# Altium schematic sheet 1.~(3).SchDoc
size 420 x 297 mm
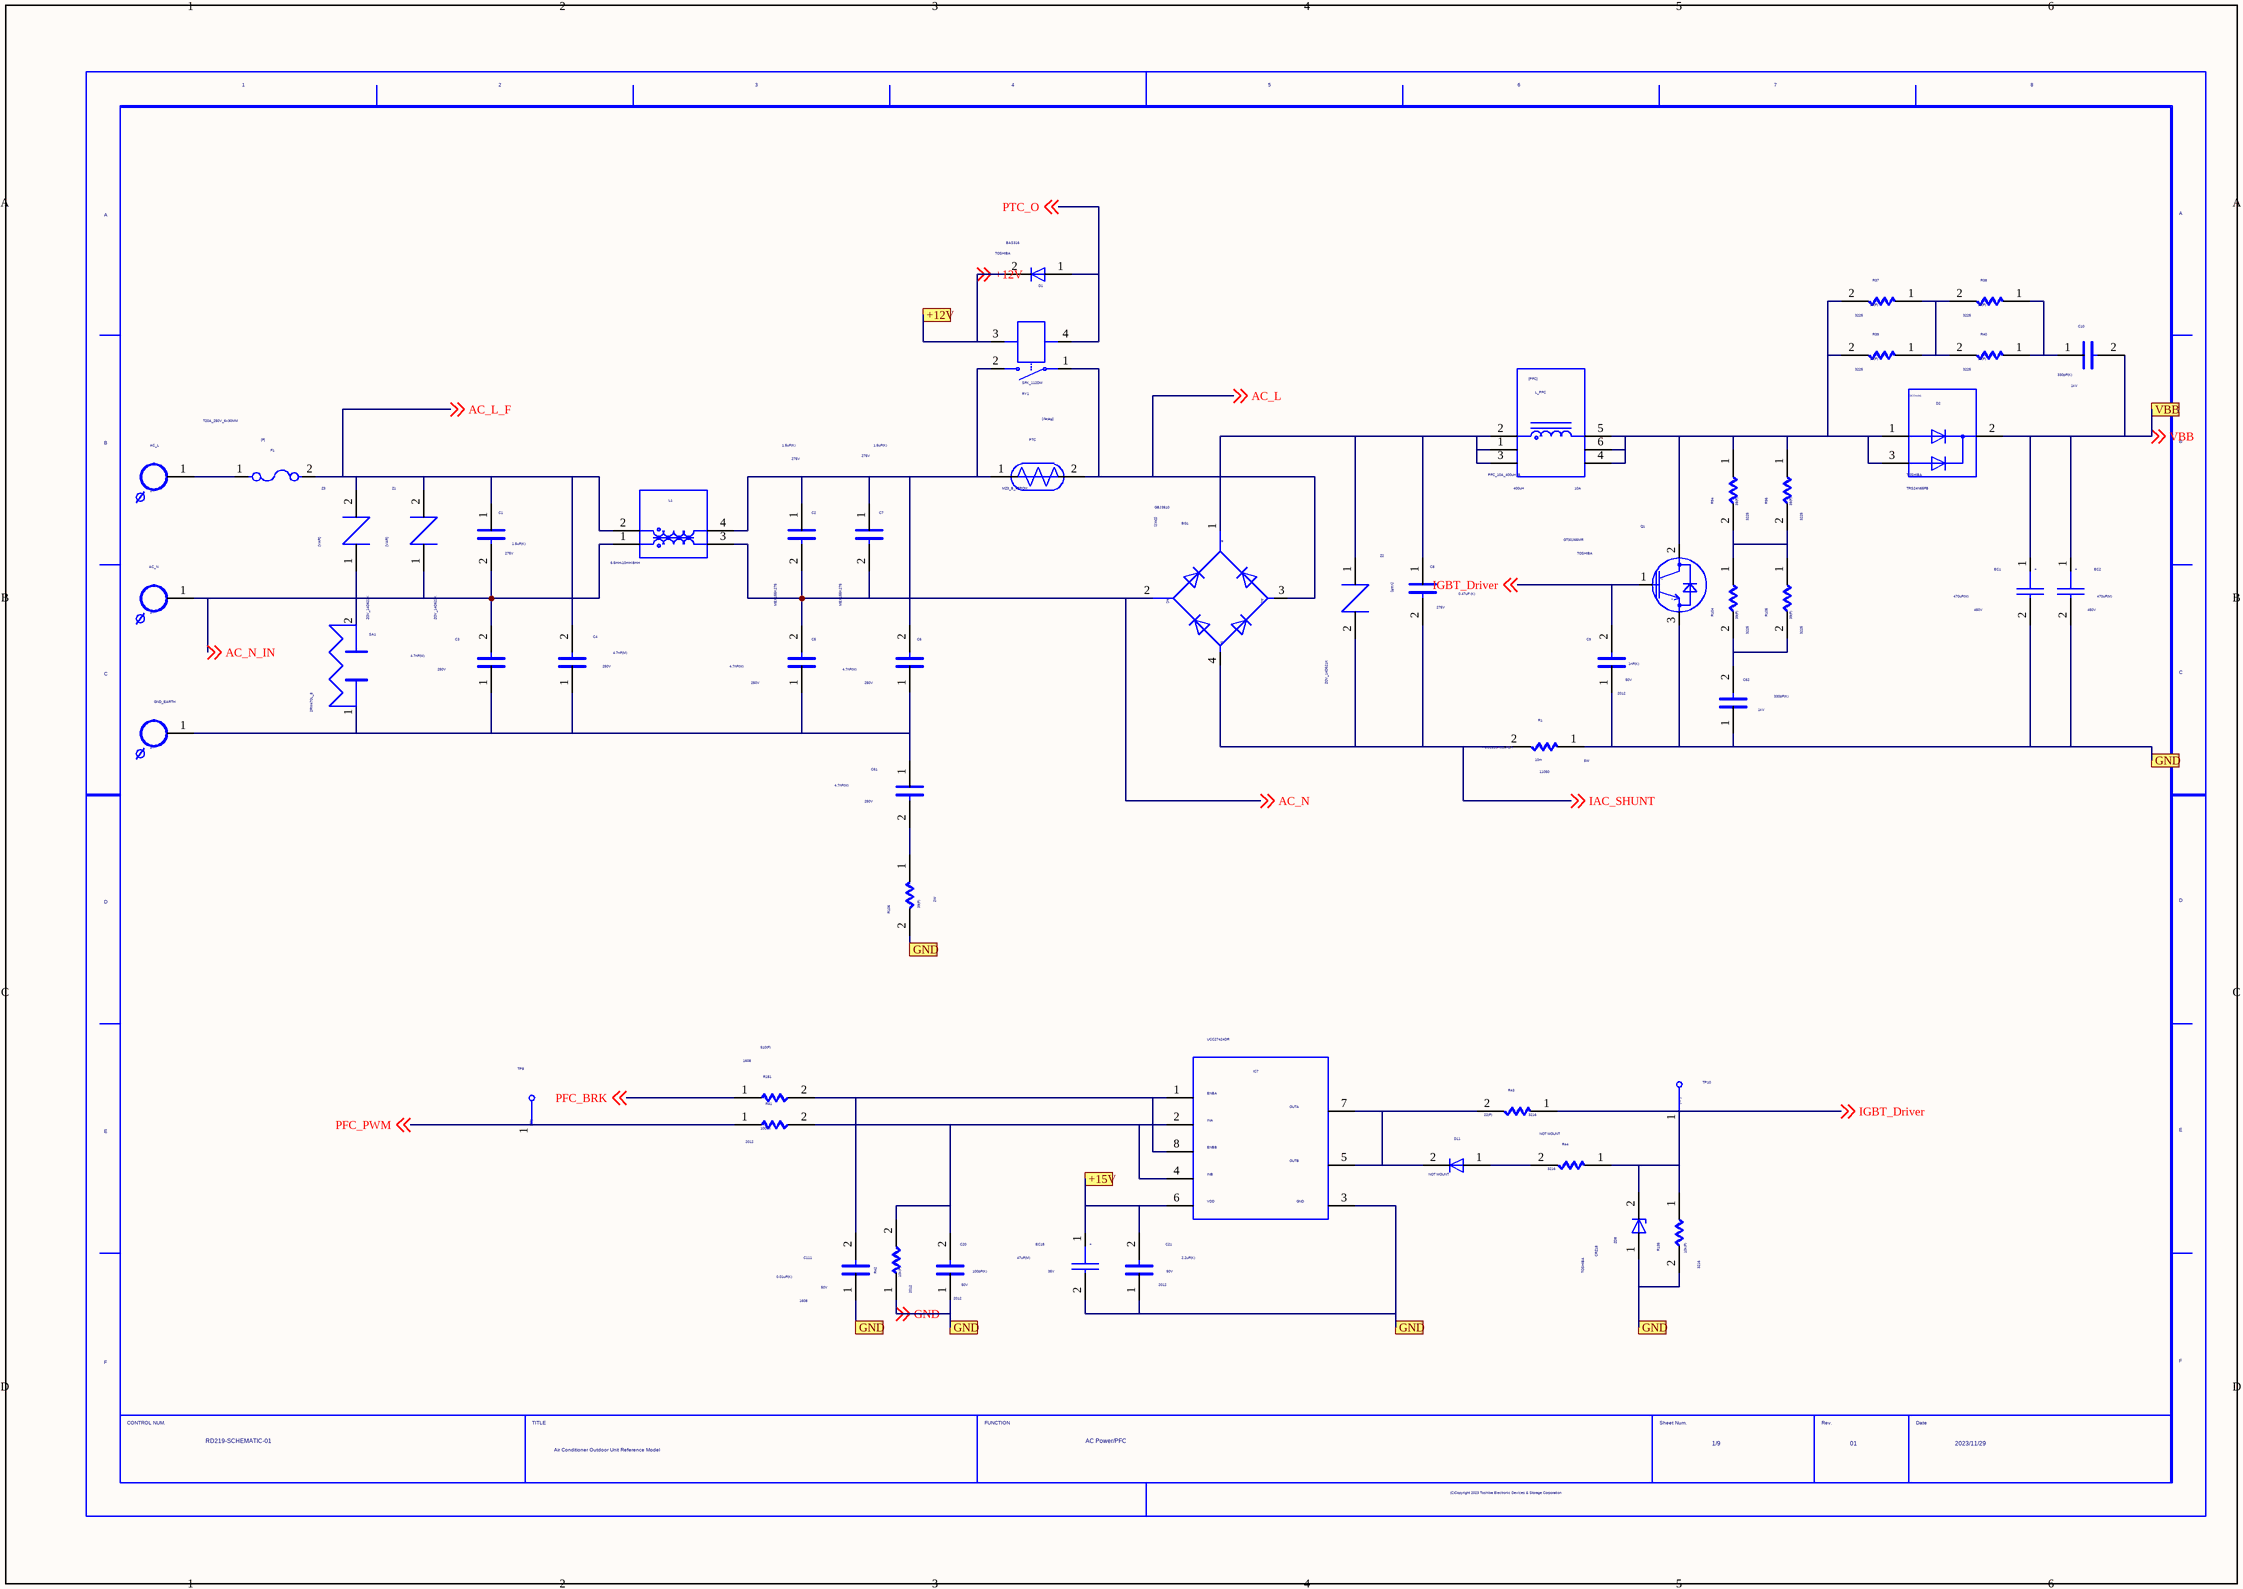
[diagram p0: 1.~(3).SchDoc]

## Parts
AC_L  TB1Y  (value not drawn)
AC_N  TB1Y  (value not drawn)
BG1  VAL1: GBJ3510  (hidden comment: DMJ)
C1  VAL2: 275V  VAL1: 1.5uF(K)  (hidden comment: C)
C2  VAL2: 275V  VAL1: 1.5uF(K)  VAL3: MEX155K275  (hidden comment: C)
C3  VAL2: 250V  VAL1: 4.7nF(M)  (hidden comment: C)
C4  VAL2: 250V  VAL1: 4.7nF(M)  (hidden comment: C)
C5  VAL2: 250V  VAL1: 4.7nF(M)  (hidden comment: C)
C6  VAL2: 250V  VAL1: 4.7nF(M)  (hidden comment: C)
C7  VAL2: 275V  VAL1: 1.5uF(K)  VAL3: MEX155K275  (hidden comment: C)
C8  VAL2: 275V  VAL1: 0.47uF (K)  (hidden comment: C)
C9  SIZECODESMD: 2012  VAL2: 50V  VAL1: 1nF(K)  (hidden comment: C)
C10  VAL2: 1kV  VAL1: 330pF(K)  (hidden comment: C)
C20  SIZECODESMD: 2012  VAL2: 50V  VAL1: 100pF(K)  (hidden comment: C)
C21  SIZECODESMD: 2012  VAL2: 50V  VAL1: 2.2uF(K)  (hidden comment: C)
C61  VAL2: 250V  VAL1: 4.7nF(M)  (hidden comment: C)
C62  VAL2: 1kV  VAL1: 330pF(K)  (hidden comment: C)
C111  SIZECODESMD: 1608  VAL2: 50V  VAL1: 0.01uF(K)  (hidden comment: C)
D1  USERCOMPTEXT3: TOSHIBA  VAL3: BAS316  (hidden comment: D_CUSTOM)
D2  USERCOMPTEXT3: TOSHIBA  VAL3: TRS24N65FB  (hidden comment: TRS24N)
D11  NOTMOUNT: NOT MOUNT  (hidden comment: D_CUSTOM)
EC1  VAL2: 450V  VAL1: 470uF(M)  (hidden comment: EC)
EC2  VAL2: 450V  VAL1: 470uF(M)  (hidden comment: EC)
EC15  VAL2: 35V  VAL1: 47uF(M)  (hidden comment: EC)
F1  COMP: T20A_250V_6x30MM  (hidden comment: F)
GND_EARTH  TB1Y  (value not drawn)
IC7  VAL1: UCC27424DR  (hidden comment: UCC27424)
L1  COMPCOMMENT: 6.5mH-10mH:8mH  (hidden comment: L2Y)
L_PFC  VAL3: PFC_10A_400uH_B  VAL2: 10A  VAL1: 400uH  (hidden comment: PFC)
PTC  VAL1: MZ3_B_47ROM  (hidden comment: PTC)
Q1  USERCOMPTEXT3: TOSHIBA  VAL3: GT30J65MR  (hidden comment: IGBT)
R1  SIZECODESMD: 11050  VAL3: FCSL110R010FER  VAL2: 5W  VAL1: 10m  (hidden comment: R)
R37  SIZECODESMD: 3225  VAL1: 39(F)  (hidden comment: R)
R38  SIZECODESMD: 3225  VAL1: 39(F)  (hidden comment: R)
R39  SIZECODESMD: 3225  VAL1: 39(F)  (hidden comment: R)
R40  SIZECODESMD: 3225  VAL1: 39(F)  (hidden comment: R)
R41  SIZECODESMD: 2012  VAL1: 100(F)  (hidden comment: R)
R42  SIZECODESMD: 2012  VAL1: 10k(F)  (hidden comment: R)
R43  SIZECODESMD: 3216  VAL1: 22(F)  (hidden comment: R)
R44  SIZECODESMD: 3216  NOTMOUNT: NOT MOUNT  (hidden comment: R)
R94  SIZECODESMD: 3225  VAL1: 39(F)  (hidden comment: R)
R96  SIZECODESMD: 3225  VAL1: 39(F)  (hidden comment: R)
R104  SIZECODESMD: 3225  VAL1: 39(F)  (hidden comment: R)
R105  SIZECODESMD: 3225  VAL1: 39(F)  (hidden comment: R)
R106  VAL2: 2W  VAL1: 39(F)  (hidden comment: R)
R135  SIZECODESMD: 3216  VAL1: 10k(F)  (hidden comment: R)
R151  SIZECODESMD: 1608  VAL1: 510(F)  (hidden comment: R)
RY1  VAL1: SFK_112DM  (hidden comment: SFK-112)
SA1  COMP: 2RM470L_8  (hidden comment: GDT)
TP8  TP  (value not drawn)
TP10  TP  (value not drawn)
U?  DATE: 2023/11/29  TITLE: Air Conditioner Outdoor Unit / Reference Model  SHEETNUMBER: 1/9  FUNCTION: AC Power/PFC  REVISION: 01  DRAWINGNUMBER: RD219-SCHEMATIC-01  (hidden comment: WAKU_DEF100)
Z1  VAL3: ZOV_14D621K  (hidden comment: VAR)
Z2  VAL3: ZOV_14D621K  (hidden comment: VAR)
Z3  VAL3: ZOV_14D621K  (hidden comment: VAR)
ZD8  USERCOMPTEXT3: TOSHIBA  VAL1: CRZ18  (hidden comment: ZD)

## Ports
+12V, +15V, GND, VBB

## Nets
+12V: D1.2 RY1.3 ; off-sheet +12V, port +12V
+15V: C21.2 EC15.1 IC7.6 ; port +15V
AC_L: BG1.3 PTC.2 RY1.1 ; off-sheet AC_L
AC_L_F: C1.1 C4.2 F1.2 L1.2 Z1.2 Z3.2 ; off-sheet AC_L_F
AC_N: BG1.2 C2.2 C5.2 C7.2 L1.3 ; off-sheet AC_N
AC_N_IN: AC_N.1 C1.2 C3.2 L1.1 Z1.1 ; off-sheet AC_N_IN
GND: C9.1 C20.1 C21.1 C62.1 C111.1 EC1.2 EC2.2 EC15.2 IC7.3 Q1.3 R1.1 R42.1 R106.2 R135.2 ZD8.1(A) ; off-sheet GND, port GND
IAC_SHUNT: BG1.4 C8.2 R1.2 Z2.2 ; off-sheet IAC_SHUNT
IGBT_Driver: C9.2 Q1.1 R43.1 R44.1 R135.1 TP10.1 ZD8.2(C) ; off-sheet IGBT_Driver
NetAC_L_1: AC_L.1 F1.1
NetBG1_1: BG1.1 C8.1 L_PFC.1 L_PFC.2 L_PFC.3 Z2.1
NetC2_1: C2.1 C6.2 C7.1 L1.4 PTC.1 RY1.2
NetC3_1: C3.1 C4.1 C5.1 C6.1 C61.1 GND_EARTH.1 SA1.1
NetC10_1: C10.1 R38.1 R40.1
NetC20_2: C20.2 IC7.2 IC7.4 R41.2 R42.2
NetC61_2: C61.2 R106.1
NetC62_2: C62.2 R104.2 R105.2
NetC111_2: C111.2 IC7.1 IC7.8 R151.2
NetD2_1: D2.1 D2.3 L_PFC.4 L_PFC.5 L_PFC.6 Q1.2 R37.2 R39.2 R94.1 R96.1
NetD11_1: D11.1 R44.2
NetD11_2: D11.2 IC7.5 IC7.7 R43.2
NetR37_1: R37.1 R38.2 R39.1 R40.2
NetR94_2: R94.2 R96.2 R104.1 R105.1
NetSA1_2: SA1.2 Z3.1
PFC_BRK: R151.1 ; off-sheet PFC_BRK
PFC_PWM: R41.1 TP8.1 ; off-sheet PFC_PWM
PTC_O: D1.1 RY1.4 ; off-sheet PTC_O
VBB: C10.2 D2.2 EC1.1 EC2.1 ; off-sheet VBB, port VBB

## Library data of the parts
AC_L = TB1Y: SAVEAREA0: -4386,-117,16897,10471; TIME: 15:17:35; UPDATEUSER: w20165dm; SAVECOUNT: 1; OriginalSymbolOrigin: (0,7620); VAL3: AC-L; COMP: PAD
AC_N = TB1Y: SAVEAREA0: -4386,-117,16897,10471; TIME: 15:17:35; UPDATEUSER: w20165dm; SAVECOUNT: 1; OriginalSymbolOrigin: (0,7620); VAL3: AC-N; COMP: PAD
BG1 = DMJ: SAVECOUNT: 8; SAVEAREA0: -14111,-292,39054,26173; TIME: 10:09:47; UPDATEUSER: 19990028; UPDATETIME: 09:28:12; OriginalSymbolOrigin: (0,25400)
C1 = C_Dup1: OriginalSymbolOrigin: (2540,7620); VAL3: MEX155K275
C2 C7 = C_Dup1: OriginalSymbolOrigin: (2540,7620)
C3-C6 C61 = C_Dup1: OriginalSymbolOrigin: (2540,7620); VAL3: DE1E3KX472MA4BN01F; COMP: JN472M
C8 = C_Dup1: OriginalSymbolOrigin: (2540,7620); COMPCOMMENT: MKP474/275VAC; VAL3: MEX474K275
C9 = C_Dup1: OriginalSymbolOrigin: (2540,7620); VAL3: AC0805KRX7R9BB102
C10 C62 = C_Dup1: OriginalSymbolOrigin: (2540,7620); VAL3: CK45-B3AD331KYGNA; COMP: 331_1KV
C20 = C: OriginalSymbolOrigin: (2540,7620); VAL3: AC0805KRX7R9BB101
C21 = C: OriginalSymbolOrigin: (2540,7620); COMP: AC0805KRX7R9BB225
C111 = C: OriginalSymbolOrigin: (2540,7620); VAL3: GCM188R71H103KA37D
D1 = D_CUSTOM: SAVEAREA0: -1668,-97,14265,7829; SAVECOUNT: 4; TIME: 14:49:55; UPDATEUSER: w20165dm; UPDATETIME: 16:47:49; OriginalSymbolOrigin: (5080,5080)
D2 = TRS24N: SAVEAREA0: -10023,-235,32546,20943; TIME: 17:15:17; UPDATEUSER: w20165dm; SAVECOUNT: 1; OriginalSymbolOrigin: (5080,20320)
D11 = D_CUSTOM: SAVEAREA0: -1668,-97,14265,7829; SAVECOUNT: 4; TIME: 14:49:55; UPDATEUSER: w20165dm; UPDATETIME: 16:47:49; OriginalSymbolOrigin: (5080,5080); COMP: 1N4148
EC1 EC2 = EC: SAVEAREA0: -1432,-1528,20311,14389; SAVECOUNT: 53; TIME: 15:02:55; UPDATEUSER: w20165dm; UPDATETIME: 16:35:05; OriginalSymbolOrigin: (2540,10160); VAL3: 450VXG470MEFCSN35X45
EC15 = EC: SAVEAREA0: -1432,-1528,20311,14389; SAVECOUNT: 53; TIME: 15:02:55; UPDATEUSER: w20165dm; UPDATETIME: 16:35:05; OriginalSymbolOrigin: (2540,10160); VAL3: CS1V470M_CRE54
F1 = F: OriginalSymbolOrigin: (2540,5080); VAL2: 250V; VAL1: 20A
GND_EARTH = TB1Y: SAVEAREA0: -4386,-117,16897,10471; TIME: 15:17:35; UPDATEUSER: w20165dm; SAVECOUNT: 1; OriginalSymbolOrigin: (0,7620); VAL3: GND_EARTH; COMP: PAD
IC7 = UCC27424: SAVEAREA0: -18701,-404,54363,35945; TIME: 14:53:37; UPDATEUSER: w20165dm; UPDATETIME: 17:37:13; SAVECOUNT: 7; OriginalSymbolOrigin: (5080,33020)
L1 = L2Y: SAVEAREA0: -7346,-206,29901,18324; TIME: 15:13:45; UPDATEUSER: w20165dm; SAVECOUNT: 1; OriginalSymbolOrigin: (5080,15240); VAL2: 20A; VAL1: 6.5mH-10mH; COMP: INDUCTOR_IRON_DOT
L_PFC = PFC: SAVEAREA0: -15388,-294,37822,26178; TIME: 13:55:27; UPDATEUSER: w20165dm; SAVECOUNT: 1; OriginalSymbolOrigin: (5080,22860); COMPCOMMENT: Inductor Iron Dot
PTC = PTC: TIME: 17:09:47; UPDATEUSER: w20165dm; UPDATETIME: 17:16:29; SAVECOUNT: 2; SAVEAREA0: -4525,-147,22079,13088; OriginalSymbolOrigin: (5080,7620)
Q1 = IGBT: TIME: 09:39:04; UPDATEUSER: w20165dm; UPDATETIME: 16:59:47; SAVECOUNT: 10; SAVEAREA0: -8472,-176,23454,15707; OriginalSymbolOrigin: (2540,12700)
R1 = R_Dup1: OriginalSymbolOrigin: (5080,5080)
R37 R38 R40 = R_Dup1: OriginalSymbolOrigin: (5080,5080); VAL3: AC1210FR-0739RL; VAL2: 500mW; COMP: AC1210FR_0739RL
R39 = R_Dup1: OriginalSymbolOrigin: (5080,5080); VAL2: 500mW; COMP: AC1210FR_0739RL; VAL3: AC1210FR-0739RL
R41 = R: OriginalSymbolOrigin: (5080,5080); VAL3: AC0805FR-07100RL; VAL2: 125mW; COMP: AC0805FR_07100RL
R42 = R: OriginalSymbolOrigin: (5080,5080); VAL3: AC0805FR-0710KL; VAL2: 125mW; COMP: AC0805FR_0710KL
R43 = R: OriginalSymbolOrigin: (5080,5080); VAL2: 250mW; VAL3: AC1206FR-0722RL; COMP: AC1206FR_0722RL
R44 = R: OriginalSymbolOrigin: (5080,5080); COMP: SMT_1206_R
R94 R104 = R_Dup1: OriginalSymbolOrigin: (5080,5080); VAL2: 500mW; VAL3: AC1210FR_0739RL
R96 R105 = R_Dup1: OriginalSymbolOrigin: (5080,5080); VAL3: AC1210FR_0739RL; VAL2: 500mW
R106 = R_Dup1: OriginalSymbolOrigin: (5080,5080); VAL3: MFR2WSFTE73_39R
R135 = R: OriginalSymbolOrigin: (5080,5080); VAL3: AC1206FR_0710KL; VAL2: 250mW
R151 = R: OriginalSymbolOrigin: (5080,5080); VAL3: AC0603FR_07510RL; VAL2: 100mW
RY1 = SFK-112: SAVEAREA0: -13231,-231,28521,20540; TIME: 14:06:16; UPDATEUSER: w20165dm; UPDATETIME: 17:57:42; SAVECOUNT: 24; OriginalSymbolOrigin: (2540,12700)
SA1 = GDT: TIME: 16:28:26; UPDATEUSER: w20165dm; UPDATETIME: 16:32:17; SAVECOUNT: 3; SAVEAREA0: -9109,-176,22817,15707; OriginalSymbolOrigin: (0,15240); VAL3: 2RM470L-8; VAL2: 10kA; VAL1: 470V
TP8 TP10 = TP_Dup1: TIME: 16:12:21; UPDATEUSER: fukuda-y; UPDATETIME: 16:18:11; SAVECOUNT: 2; SAVEAREA0: -242,-92,12810,7836; OriginalSymbolOrigin: (0,7620); VAL3: ZXD
U? = WAKU_DEF100: PLOTTIME: HH:MM; SAVEAREA0: -45080,-4508,463680,304612; TIME: 17:28:05; UPDATEUSER: sptcae13; UPDATETIME: 08:19:30; SAVECOUNT: 8; OriginalSymbolOrigin: (10160,284480)
Z1 Z3 = VAR: SAVEAREA0: -418,-1801,15408,7141; SAVECOUNT: 5; OriginalSymbolOrigin: (5080,5080)
Z2 = VAR: SAVEAREA0: -418,-1801,15408,7141; SAVECOUNT: 5; OriginalSymbolOrigin: (5080,5080); COMP: ZOV_14D621K_18MM
ZD8 = ZD: SAVEAREA0: -4071,-115,16804,10270; TIME: 09:43:08; UPDATEUSER: w20165dm; UPDATETIME: 16:32:57; SAVECOUNT: 6; OriginalSymbolOrigin: (5080,5080)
